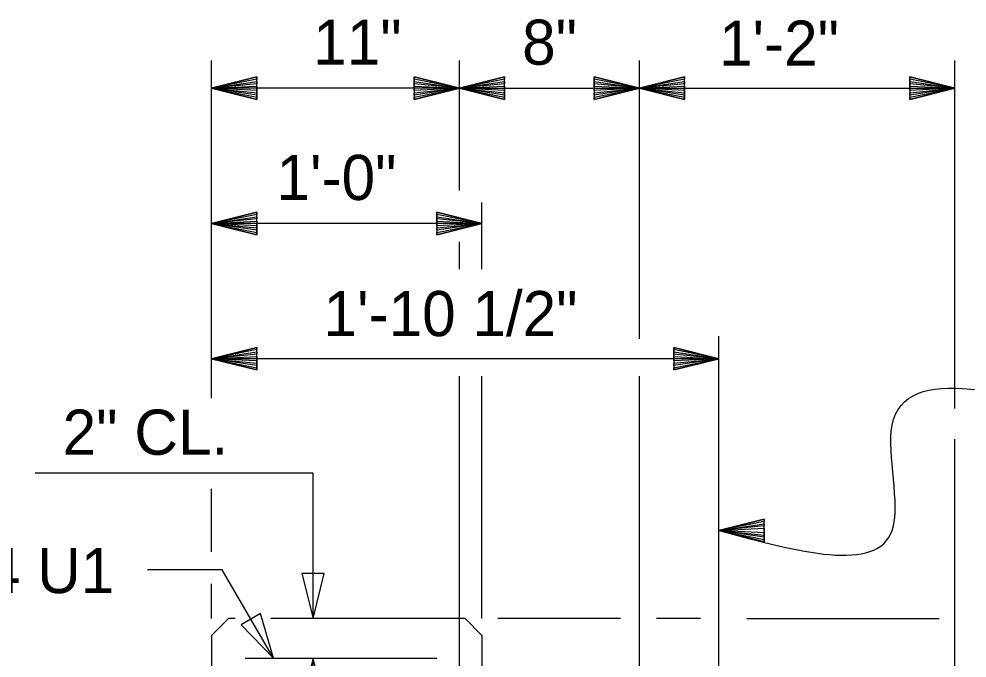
# Model space of a CAD drawing. Extents: x -41 to 251, y -169 to 237.
# Drawn here: x 45.01 to 51.02, y -148.21 to -144.17 of the extents above; entities that cross this region are included whole.
import ezdxf

# ---------------------------------------------------------------- set-up
doc = ezdxf.new("R2010")
doc.units = 0
for name, color, linetype in [('Arrowhead Terminators CELL', 7, 'Continuous'), ('Dimension Lines', 7, 'Continuous'), ('Dimension Lines CELL', 7, 'Continuous'), ('Rebar Lines CELL', 7, 'Continuous'), ('sub interior bent cap lines', 7, 'Continuous'), ('Text CELL', 7, 'Continuous')]:
    doc.layers.add(name, color=color, linetype=linetype)

msp = doc.modelspace()

# ---------------------------------------------------------------- linework, layer by layer
at = {"layer": 'Arrowhead Terminators CELL'}
for points in [[(46.5205, -144.6056), (46.5205, -144.62), (46.2344, -144.6056), (46.5205, -144.6343), (46.5205, -144.6485), (46.2344, -144.6056), (46.5205, -144.6629), (46.5205, -144.6771), (46.2344, -144.6056), (46.5205, -144.5342), (46.5205, -144.5485), (46.2344, -144.6056), (46.5205, -144.5627), (46.5205, -144.577), (46.2344, -144.6056), (46.5205, -144.5914), (46.5205, -144.6771), (46.5205, -144.5342), (46.2344, -144.6056), (46.5205, -144.6771)], [(47.518, -144.6056), (47.518, -144.5914), (47.804, -144.6056), (47.518, -144.577), (47.518, -144.5627), (47.804, -144.6056), (47.518, -144.5485), (47.518, -144.5342), (47.804, -144.6056), (47.518, -144.6771), (47.518, -144.6629), (47.804, -144.6056), (47.518, -144.6485), (47.518, -144.6343), (47.804, -144.6056), (47.518, -144.62), (47.518, -144.5342), (47.518, -144.6771), (47.804, -144.6056), (47.518, -144.5342)], [(48.0901, -144.6056), (48.0901, -144.62), (47.804, -144.6056), (48.0901, -144.6343), (48.0901, -144.6485), (47.804, -144.6056), (48.0901, -144.6629), (48.0901, -144.6771), (47.804, -144.6056), (48.0901, -144.5342), (48.0901, -144.5485), (47.804, -144.6056), (48.0901, -144.5627), (48.0901, -144.577), (47.804, -144.6056), (48.0901, -144.5914), (48.0901, -144.6771), (48.0901, -144.5342), (47.804, -144.6056), (48.0901, -144.6771)], [(48.6588, -144.6056), (48.6588, -144.5914), (48.9448, -144.6056), (48.6588, -144.577), (48.6588, -144.5627), (48.9448, -144.6056), (48.6588, -144.5485), (48.6588, -144.5342), (48.9448, -144.6056), (48.6588, -144.6771), (48.6588, -144.6629), (48.9448, -144.6056), (48.6588, -144.6485), (48.6588, -144.6343), (48.9448, -144.6056), (48.6588, -144.62), (48.6588, -144.5342), (48.6588, -144.6771), (48.9448, -144.6056), (48.6588, -144.5342)], [(49.2309, -144.6056), (49.2309, -144.62), (48.9448, -144.6056), (49.2309, -144.6343), (49.2309, -144.6485), (48.9448, -144.6056), (49.2309, -144.6629), (49.2309, -144.6771), (48.9448, -144.6056), (49.2309, -144.5342), (49.2309, -144.5485), (48.9448, -144.6056), (49.2309, -144.5627), (49.2309, -144.577), (48.9448, -144.6056), (49.2309, -144.5914), (49.2309, -144.6771), (49.2309, -144.5342), (48.9448, -144.6056), (49.2309, -144.6771)], [(50.6565, -144.6056), (50.6565, -144.5914), (50.9425, -144.6056), (50.6565, -144.577), (50.6565, -144.5627), (50.9425, -144.6056), (50.6565, -144.5485), (50.6565, -144.5342), (50.9425, -144.6056), (50.6565, -144.6771), (50.6565, -144.6629), (50.9425, -144.6056), (50.6565, -144.6485), (50.6565, -144.6343), (50.9425, -144.6056), (50.6565, -144.62), (50.6565, -144.5342), (50.6565, -144.6771), (50.9425, -144.6056), (50.6565, -144.5342)], [(46.5205, -145.4618), (46.5205, -145.4761), (46.2344, -145.4618), (46.5205, -145.4904), (46.5205, -145.5047), (46.2344, -145.4618), (46.5205, -145.519), (46.5205, -145.5333), (46.2344, -145.4618), (46.5205, -145.3903), (46.5205, -145.4046), (46.2344, -145.4618), (46.5205, -145.4189), (46.5205, -145.4331), (46.2344, -145.4618), (46.5205, -145.4475), (46.5205, -145.5333), (46.5205, -145.3903), (46.2344, -145.4618), (46.5205, -145.5333)], [(47.6607, -145.4618), (47.6607, -145.4475), (47.9467, -145.4618), (47.6607, -145.4331), (47.6607, -145.4189), (47.9467, -145.4618), (47.6607, -145.4046), (47.6607, -145.3903), (47.9467, -145.4618), (47.6607, -145.5333), (47.6607, -145.519), (47.9467, -145.4618), (47.6607, -145.5047), (47.6607, -145.4904), (47.9467, -145.4618), (47.6607, -145.4761), (47.6607, -145.3903), (47.6607, -145.5333), (47.9467, -145.4618), (47.6607, -145.3903)], [(46.5205, -146.3179), (46.5205, -146.3322), (46.2344, -146.3179), (46.5205, -146.3465), (46.5205, -146.3608), (46.2344, -146.3179), (46.5205, -146.3751), (46.5205, -146.3894), (46.2344, -146.3179), (46.5205, -146.2464), (46.5205, -146.2607), (46.2344, -146.3179), (46.5205, -146.275), (46.5205, -146.2893), (46.2344, -146.3179), (46.5205, -146.3036), (46.5205, -146.3894), (46.5205, -146.2464), (46.2344, -146.3179), (46.5205, -146.3894)], [(49.162, -146.3179), (49.162, -146.3036), (49.4481, -146.3179), (49.162, -146.2893), (49.162, -146.275), (49.4481, -146.3179), (49.162, -146.2607), (49.162, -146.2464), (49.4481, -146.3179), (49.162, -146.3894), (49.162, -146.3751), (49.4481, -146.3179), (49.162, -146.3608), (49.162, -146.3465), (49.4481, -146.3179), (49.162, -146.3322), (49.162, -146.2464), (49.162, -146.3894), (49.4481, -146.3179), (49.162, -146.2464)], [(49.7341, -147.4056), (49.7341, -147.4198), (49.4481, -147.4056), (49.7341, -147.4342), (49.7341, -147.4485), (49.4481, -147.4056), (49.7341, -147.4628), (49.7341, -147.4771), (49.4481, -147.4056), (49.7341, -147.334), (49.7341, -147.3483), (49.4481, -147.4056), (49.7341, -147.3627), (49.7341, -147.3769), (49.4481, -147.4056), (49.7341, -147.3913), (49.7341, -147.4771), (49.7341, -147.334), (49.4481, -147.4056), (49.7341, -147.4771)]]:
    msp.add_lwpolyline(points, dxfattribs=at)
for points in [[(46.8773, -147.9632), (46.9485, -147.6786), (46.8061, -147.6786)], [(46.6276, -148.213), (46.5454, -147.9313), (46.4226, -148.0031)], [(46.8773, -148.213), (46.8061, -148.4977), (46.9485, -148.4977)]]:
    msp.add_lwpolyline(points, close=True, dxfattribs=at)
at = {"layer": 'Dimension Lines'}
msp.add_line((49.4481, -148.4969), (49.4481, -146.1748), dxfattribs=at)
at = {"layer": 'Dimension Lines CELL'}
for p, q in [((46.2344, -146.5687), (46.2344, -144.4298)), ((47.804, -145.253), (47.804, -144.4298)), ((48.9448, -146.1911), (48.9448, -144.4298)), ((50.9425, -146.6342), (50.9425, -144.4298)), ((47.804, -144.6056), (46.2344, -144.6056)), ((47.804, -144.6056), (48.9448, -144.6056)), ((48.9448, -144.6056), (50.9425, -144.6056)), ((47.9467, -145.7508), (47.9467, -145.3296)), ((47.9467, -145.4618), (46.2344, -145.4618)), ((47.804, -145.7508), (47.804, -145.5785)), ((49.445, -146.3179), (46.2344, -146.3179)), ((47.804, -151.4767), (47.804, -146.4285)), ((47.9467, -147.9632), (47.9467, -146.4285)), ((48.9448, -151.4767), (48.9448, -146.4285)), ((50.9425, -149.8784), (50.9425, -146.8266)), ((46.8773, -147.0416), (45.1182, -147.0416)), ((46.8773, -147.9632), (46.8773, -147.0416)), ((46.2344, -147.5414), (46.2344, -147.1418)), ((46.2344, -147.9632), (46.2344, -147.7439)), ((48.8239, -147.9632), (48.0468, -147.9632)), ((49.3316, -147.9632), (49.0521, -147.9632)), ((49.6245, -147.9632), (50.843, -147.9632)), ((46.8773, -148.7373), (46.8773, -148.213))]:
    msp.add_line(p, q, dxfattribs=at)
msp.add_lwpolyline([(46.6276, -148.213), (46.3014, -147.6547), (45.8286, -147.6547)], dxfattribs=at)
msp.add_spline([(49.4481, -147.4056), (50.5451, -147.4056), (50.5451, -146.7382), (51.9964, -146.7382)], degree=3, dxfattribs=at)
at = {"layer": 'Rebar Lines CELL'}
msp.add_line((46.4484, -148.213), (47.6612, -148.213), dxfattribs=at)
at = {"layer": 'sub interior bent cap lines'}
for p, q in [((46.2343, -148.0703), (46.3414, -147.9632)), ((46.3841, -147.9632), (46.3414, -147.9632)), ((47.8397, -147.9632), (46.6092, -147.9632)), ((47.9468, -148.0703), (47.8397, -147.9632))]:
    msp.add_line(p, q, dxfattribs=at)
for points in [[(46.2344, -148.0703), (46.2344, -148.8586)], [(47.9467, -148.0703), (47.9467, -150.8101)]]:
    msp.add_lwpolyline(points, dxfattribs=at)

# ---------------------------------------------------------------- texts
at = {"layer": 'Text CELL'}
for s, height, p in [('8"', 0.28539, (48.2016, -144.4566)), ('11"', 0.28539, (46.8785, -144.4566)), ('1\'-2"', 0.28539, (49.4487, -144.4626)), ('1\'-0"', 0.28539, (46.6459, -145.3128)), ('1\'-10 1/2"', 0.28539, (46.9439, -146.1748)), ('2" CL.', 0.28588, (45.2911, -146.9262)), ('#4 U1', 0.28588, (44.5987, -147.8022))]:
    msp.add_text(s, height=height, dxfattribs=at).set_placement(p)

doc.saveas('drawing.dxf')
